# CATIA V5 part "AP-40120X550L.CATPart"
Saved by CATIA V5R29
Part number: AP-40120X550L
Source: Unknown
Bounding box of the stored display mesh (mm): x -275 to 275, y -60 to 60, z -20 to 20
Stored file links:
  C:\가치같이\SmartFactory_BoxErectorConveyor\Boxing(under)\AP-40120X550L.CATPart
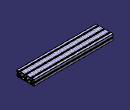
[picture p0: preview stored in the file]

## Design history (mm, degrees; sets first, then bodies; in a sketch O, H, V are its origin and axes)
Body1 (main body)
  Solid1 "PartBody": solid without history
